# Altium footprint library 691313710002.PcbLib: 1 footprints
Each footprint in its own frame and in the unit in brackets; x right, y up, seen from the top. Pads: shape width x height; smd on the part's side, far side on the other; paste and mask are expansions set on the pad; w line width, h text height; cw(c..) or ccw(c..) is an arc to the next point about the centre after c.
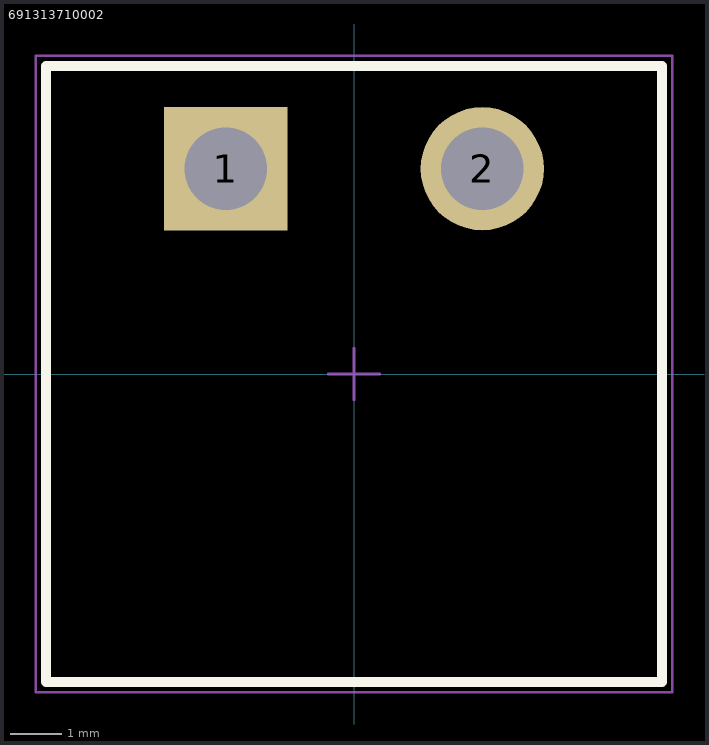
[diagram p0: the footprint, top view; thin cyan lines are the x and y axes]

## 691313710002 [mm] "5.00mm - Closed Horizhontal PCB Header - -02p"
height 8.5
pads (2):
  rect 2.4x2.4 hole 1.6: 1(-2.5,4)
  round 2.4 hole 1.6: 2(2.5,4)
Top Overlay:
  lines w0.2: -6,-6 -6,6 6,6 6,-6 -6,-6
Mechanical 13:
  lines w0.1: -6,-6 6,-6 6,6 -6,6 -6,-6
Mechanical 15:
  lines w0.05: -0.5,0 0.5,0 ; 0,-0.5 0,0.5 ; -6.2,-6.2 6.2,-6.2 6.2,6.2 -6.2,6.2 -6.2,-6.2
3D body "691313710002.stp": height 8.55, standoff -3.45, extent -6,-6 6,6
